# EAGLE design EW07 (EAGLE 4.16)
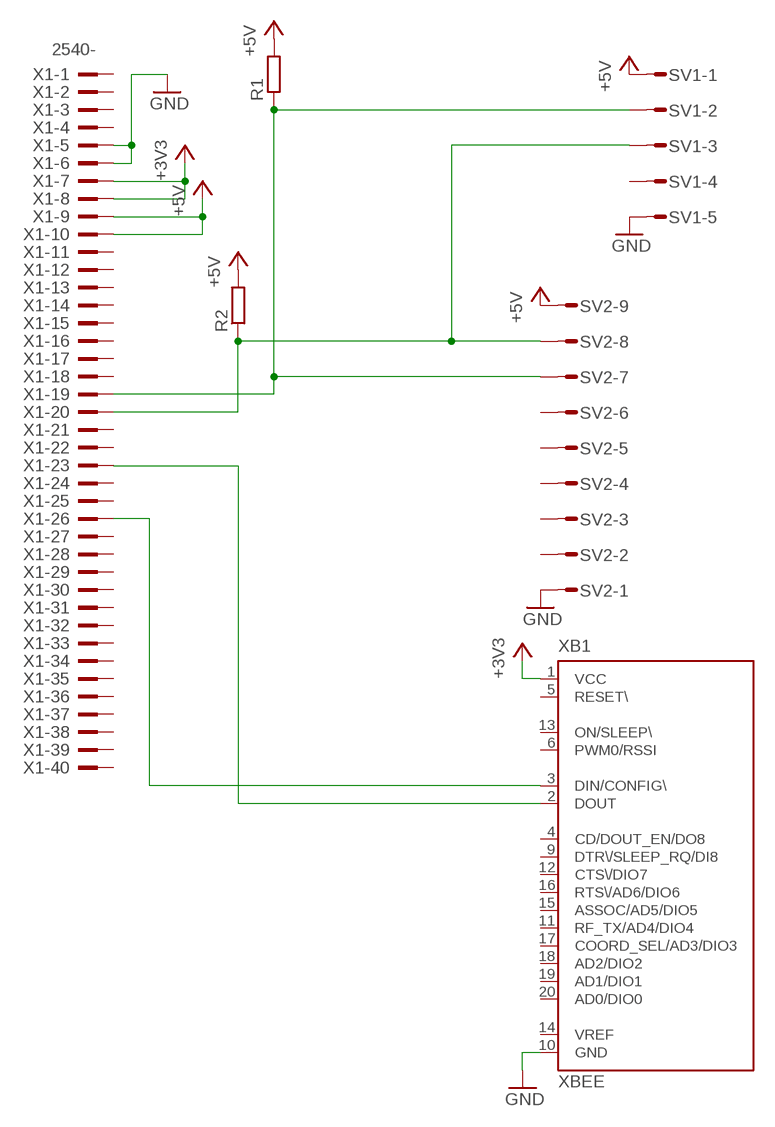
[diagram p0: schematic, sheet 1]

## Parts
R1  R-EU_0204/7  [0204/7]
R2  R-EU_0204/7  [0204/7]
SV1  S05P  [S05P]
SV2  S09P  [S09P]
X1  2540-  [PAK100/2500-40]
XB1  XBEE  [XBEE]

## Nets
+3V3: X1.7 X1.8 XB1.1(VCC)
+5V: R1.2 R2.2 SV1.1 SV2.9 X1.9 X1.10
GND: SV1.5 SV2.1 X1.5 X1.6 XB1.10(GND)
N$1: X1.23 XB1.2(DOUT)
N$2: X1.26 XB1.3(DIN/CONFIG\)
N$6: R1.1 SV1.2 SV2.7 X1.19
N$7: R2.1 SV1.3 SV2.8 X1.20
Unconnected: SV1.4 SV2.2 SV2.3 SV2.4 SV2.5 SV2.6 X1.1 X1.2 X1.3 X1.4 X1.11 X1.12 X1.13 X1.14 X1.15 X1.16 X1.17 X1.18 X1.21 X1.22 X1.24 X1.25 X1.27 X1.28 X1.29 X1.30 X1.31 X1.32 X1.33 X1.34 X1.35 X1.36 X1.37 X1.38 X1.39 X1.40 XB1.4(CD/DOUT_EN/DO8) XB1.5(RESET\) XB1.6(PWM0/RSSI) XB1.9(DTR\/SLEEP_RQ/DI8) XB1.11(RF_TX/AD4/DIO4) XB1.12(CTS\/DIO7) XB1.13(ON/SLEEP\) XB1.14(VREF) XB1.15(ASSOC/AD5/DIO5) XB1.16(RTS\/AD6/DIO6) XB1.17(COORD_SEL/AD3/DIO3) XB1.18(AD2/DIO2) XB1.19(AD1/DIO1) XB1.20(AD0/DIO0)

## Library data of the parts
R1 R2 = rcl:R-EU_: RESISTOR, European symbol
SV1 = con-amp-mt:S05P: AMP MT CONNECTOR
SV2 = con-amp-mt:S09P: AMP MT CONNECTOR
X1 = con-3m:2540-: 3M (TM) Pak 100 4-Wall Header Source: 3M
XB1 = maxstream:XBEE: XBee (TM) /XBee-PRO(TM) OEM RF Modules Source: MaxStream, Inc. xbee_productmanual.pdf

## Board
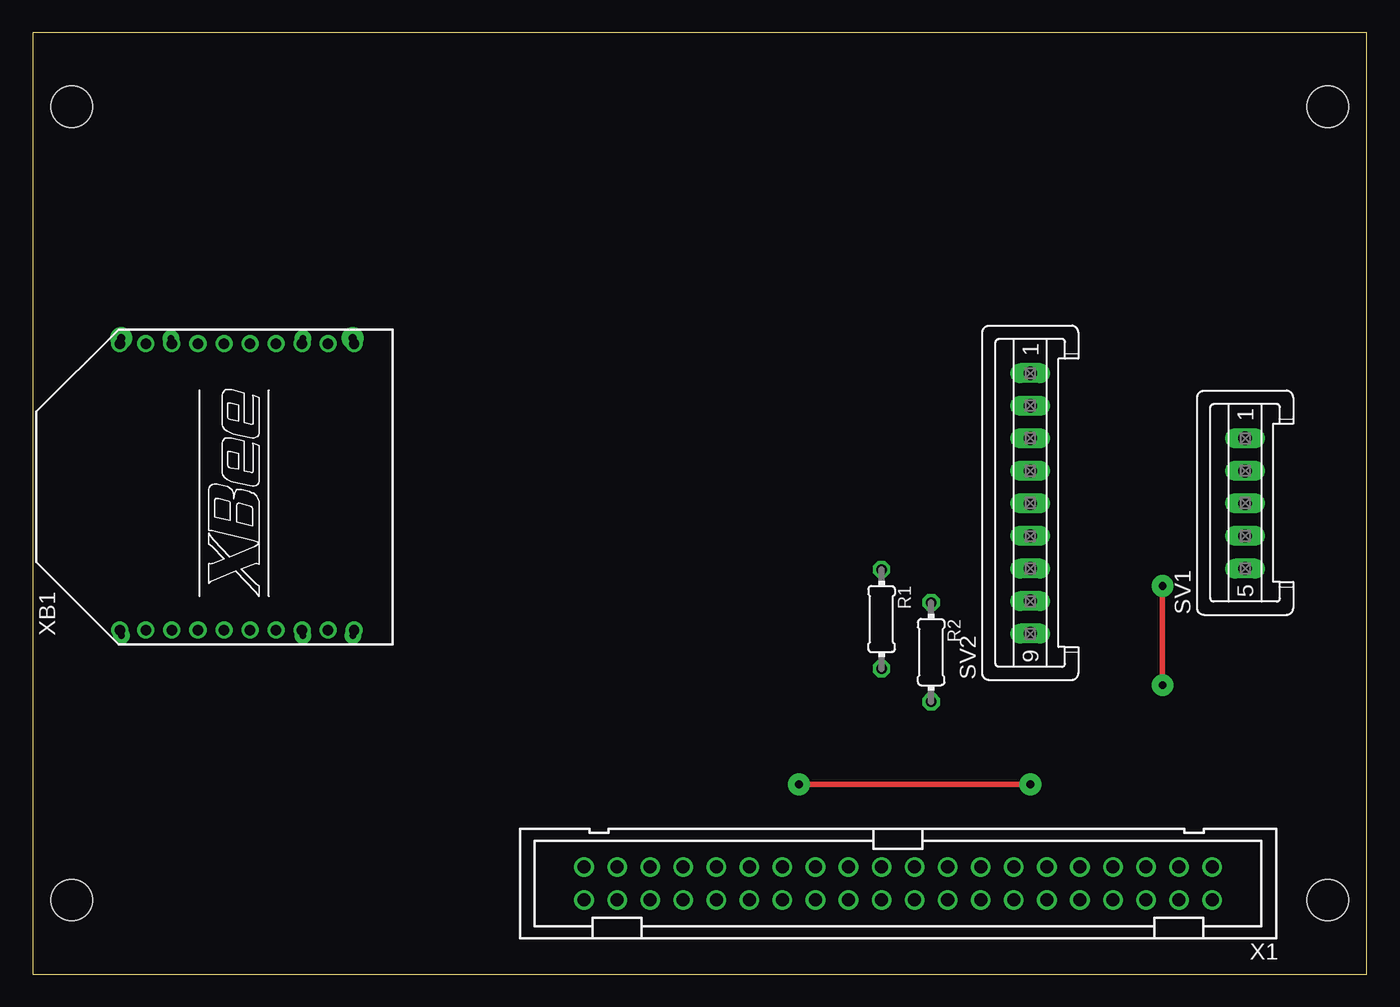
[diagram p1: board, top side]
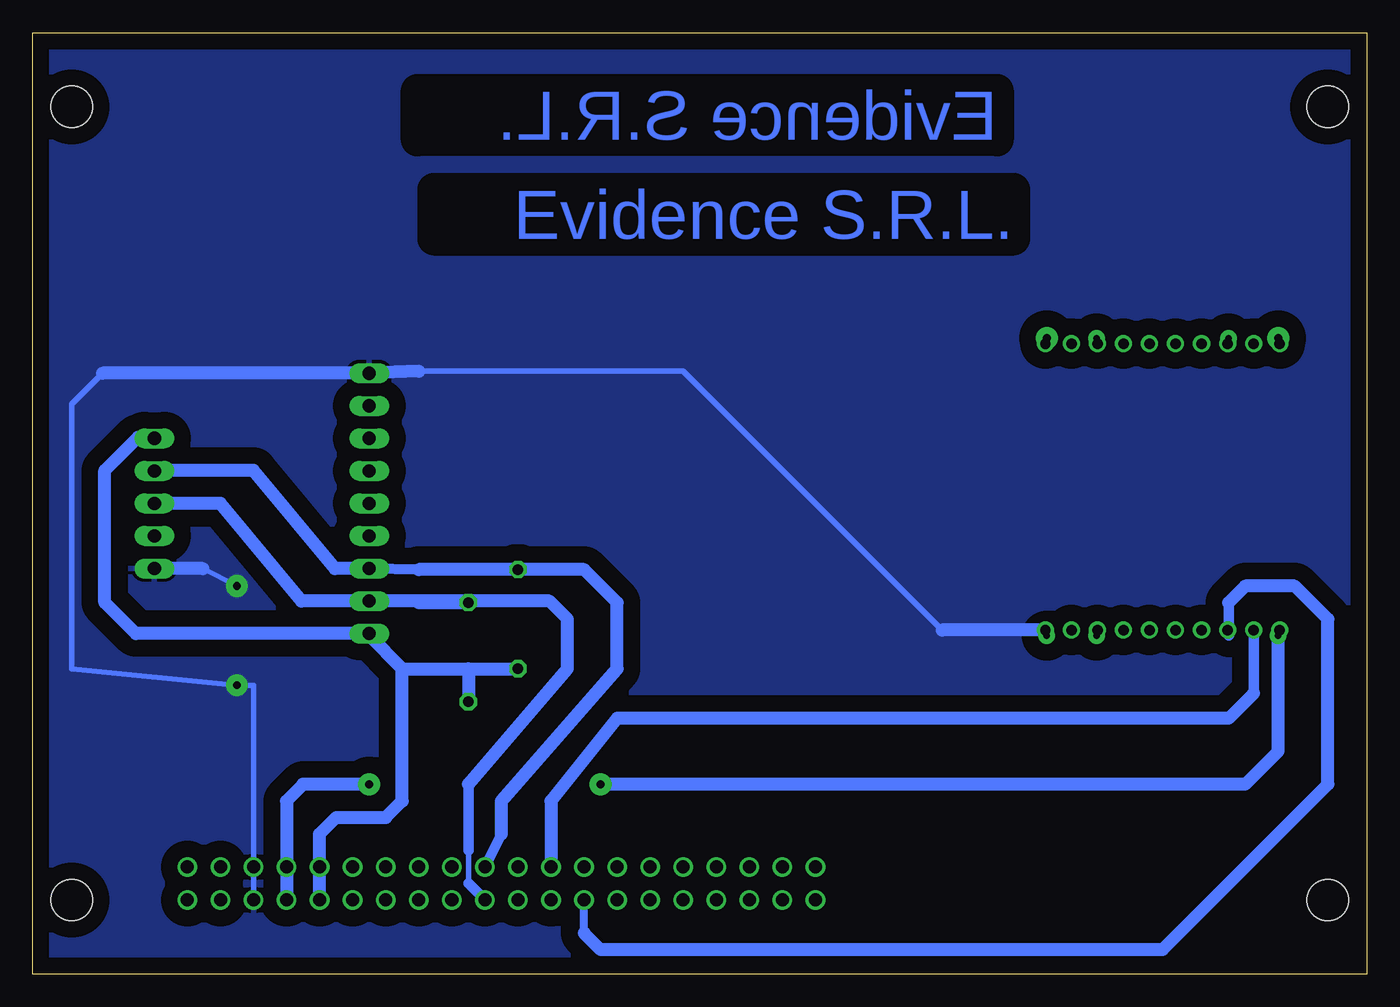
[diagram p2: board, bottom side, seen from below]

Size 102.54 x 72.38 mm. Coordinates in mm from the lower left corner, seen from the top.
Outline: 0,0 102.54,0 102.54,72.38 0,72.38 0,0
Copper layers (1*16): Top 0.035mm / dielectric 1.5mm / Bottom 0.035mm
Design rules "default": minimum track width 10mil, minimum drill 24mil, track to track 8mil, track to pad 8mil, pad to pad 8mil, via to via 8mil, smd to smd 8mil, copper to edge 40mil, drill to drill 8mil, minimum pad ring 10mil, minimum via ring 8mil, stop-mask expansion 4mil, vias tented up to drill 0mil, thermal gap 10mil
Holes 3.2 mm at 3.01,5.71 3.01,66.67 99.53,66.67 99.53,5.71

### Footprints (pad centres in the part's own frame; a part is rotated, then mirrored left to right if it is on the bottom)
0204/7 = drill 0.813 octagon: 1 -3.81,0; 2 3.81,0
S05P = drill 1.016 long: 1 5,0; 2 2.5,0; 3 0,0; 4 -2.5,0; 5 -5,0
S09P = drill 1.016 long: 1 10,0; 2 7.5,0; 3 5,0; 4 2.5,0; 5 0,0; 6 -2.5,0; 7 -5,0; 8 -7.5,0; 9 -10,0
PAK100/2500-40 = drill 1 pad 1.422 round: 1 -24.13,-1.27; 2 -24.13,1.27; 3 -21.59,-1.27; 4 -21.59,1.27; 5 -19.05,-1.27; 6 -19.05,1.27; 7 -16.51,-1.27; 8 -16.51,1.27; 9 -13.97,-1.27; 10 -13.97,1.27; 11 -11.43,-1.27; 12 -11.43,1.27; 13 -8.89,-1.27; 14 -8.89,1.27; 15 -6.35,-1.27; 16 -6.35,1.27; 17 -3.81,-1.27; 18 -3.81,1.27; 19 -1.27,-1.27; 20 -1.27,1.27; 21 1.27,-1.27; 22 1.27,1.27; 23 3.81,-1.27; 24 3.81,1.27; 25 6.35,-1.27; 26 6.35,1.27; 27 8.89,-1.27; 28 8.89,1.27; 29 11.43,-1.27; 30 11.43,1.27; 31 13.97,-1.27; 32 13.97,1.27; 33 16.51,-1.27; 34 16.51,1.27; 35 19.05,-1.27; 36 19.05,1.27; 37 21.59,-1.27; 38 21.59,1.27; 39 24.13,-1.27; 40 24.13,1.27
XBEE = drill 0.8 pad 1.27 round: 1 -11,9; 2 -11,7; 3 -11,5; 4 -11,3; 5 -11,1; 6 -11,-1; 7 -11,-3; 8 -11,-5; 9 -11,-7; 10 -11,-9; 11 11,-9; 12 11,-7; 13 11,-5; 14 11,-3; 15 11,-1; 16 11,1; 17 11,3; 18 11,5; 19 11,7; 20 11,9

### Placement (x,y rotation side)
R1  65.24,27.3 270 top
R2  69.05,24.76 270 top
SV1  93.18,36.19 90 top
SV2  76.67,36.19 90 top
X1  66.51,6.98 180 top
XB1  15.71,37.46 90 top

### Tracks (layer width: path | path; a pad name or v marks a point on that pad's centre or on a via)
+3V3  (via drill 0.5 pad 1.27, 0.6 pad 1.68)
  Top 0.406: v58.89,14.6 v76.67,14.6
  Bottom 0.406: v6.82,26.03 6.71,26.14 XB1.1
  Bottom 1.016: X1.8 X1.7 83.02,13.33 81.75,14.6 v76.67,14.6 | v58.89,14.6 9.36,14.6 6.82,17.14 v6.82,26.03
+5V
  Bottom 0.406: 76.67,26.03 SV2.9 | 94.45,41.27 SV1.1
  Bottom 1.016: 69.05,23.49 R1.2 | 74.13,23.49 69.05,23.49 | 74.13,23.49 76.67,26.03 | 69.05,23.49 R2.2 | X1.10 X1.9 80.48,10.79 79.21,12.06 75.4,12.06 74.13,13.33 74.13,23.49 | SV2.9 94.61,26.19 96.99,28.57 96.99,38.73 94.45,41.27
GND  (via drill 0.6 pad 1.68)
  Top 0.406: v86.83,22.22 v86.83,29.84
  Bottom 0.406: 32.65,26.46 52.54,46.35 72.86,46.35 | 97.15,46.19 99.53,43.81 99.53,23.49 v86.83,22.22 85.56,22.22 X1.5 X1.6 | v86.83,29.84 89.45,31.19
  Bottom 1.016: XB1.10 32.65,26.46 | 72.86,46.35 SV2.1 97.15,46.19 | 89.45,31.19 SV1.5
  pour Bottom (isolate 1.27): 0.47,71.75 102.07,71.75 102.07,0.63 0.47,0.63
N$1
  Bottom 0.813: 8.71,21.6 XB1.2
  Bottom 1.016: X1.23 62.7,13.33 57.62,19.68 10.63,19.68 8.71,21.6
N$2
  Bottom 0.406: 10.63,26.03 10.71,26.11 XB1.3
  Bottom 0.61: 60.16,3.17 X1.26
  Bottom 0.813: 10.63,28.57 10.63,26.03
  Bottom 1.016: 60.16,3.17 58.89,1.9 15.71,1.9 3.01,14.6 3.01,27.3 5.55,29.84 9.36,29.84 10.63,28.57
N$3  (via drill 0.6 pad 1.68)
  other vias: 24.6,48.89
N$4  (via drill 0.6 pad 1.68)
  other vias: 6.82,48.89
N$5  (via drill 0.5 pad 1.27)
  other vias: 24.6,26.03
N$6
  Bottom 0.406: 93.18,38.73 SV1.2
  Bottom 0.813: 72.86,31.11 SV2.7 | X1.19 66.51,10.79
  Bottom 1.016: SV2.7 79.29,31.19 85.56,38.73 93.18,38.73 | 72.86,31.11 R1.1 60.16,31.11 57.62,28.57 57.62,23.49 66.51,13.33 66.51,10.79
N$7
  Bottom 0.406: SV2.8 72.86,28.57 | 69.05,6.98 69.05,9.52
  Bottom 0.813: 69.05,9.52 69.05,14.6 | X1.20 69.05,6.98
  Bottom 1.016: 72.86,28.57 R2.1 | 69.05,14.6 61.43,23.49 61.43,27.3 62.82,28.69 SV2.8 81.87,28.69 88.1,36.19 SV1.3
N$8  (via drill 0.5 pad 1.27)
  other vias: 20.79,26.03
N$9  (via drill 0.5 pad 1.27)
  other vias: 20.79,48.89
N$10  (via drill 0.5 pad 1.27)
  other vias: 10.63,48.89

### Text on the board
Bottom: Evidence S.R.L. | Evidence S.R.L.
